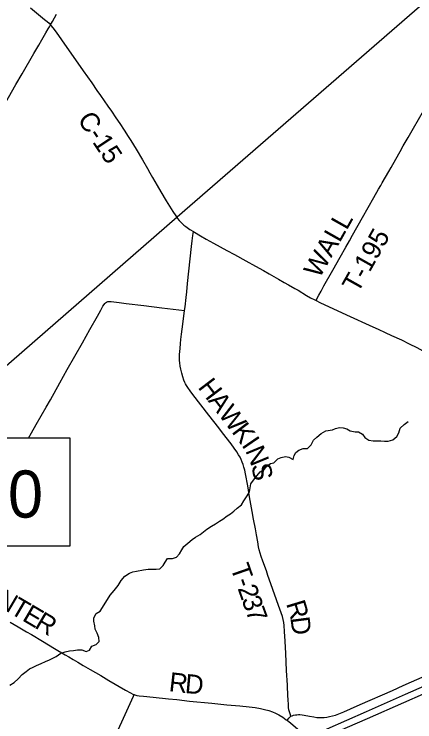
# Model space of a CAD drawing. Extents: x -1.4 to 35.4, y 0 to 22.
# Drawn here: x 6.307 to 7.497, y 14.844 to 16.946 of the extents above; entities that cross this region are included whole.
import ezdxf

# ---------------------------------------------------------------- set-up
doc = ezdxf.new("R2010")
doc.units = 0
for name, color, linetype in [('GM_X_County_Road', 7, 'Continuous'), ('GM_X_County_Road_Text', 7, 'Continuous'), ('GM_X_Interstate_Route', 7, 'Continuous'), ('GM_X_Minor_River', 7, 'Continuous'), ('GM_X_Rail_Line', 7, 'Continuous'), ('GM_X_Township_Road', 7, 'Continuous'), ('GM_X_Township_Road_Text', 7, 'Continuous'), ('SH_Data', 7, 'Continuous')]:
    doc.layers.add(name, color=color, linetype=linetype)

msp = doc.modelspace()

# ---------------------------------------------------------------- linework, layer by layer
at = {"layer": 'GM_X_County_Road'}
for points in [[(6.3553, 16.9645), (6.3974, 16.9305), (6.4045, 16.9244), (6.4103, 16.9187), (6.4148, 16.9138)], [(6.4148, 16.9138), (6.4202, 16.9236), (6.433, 16.9463)], [(6.1314, 16.4238), (6.133, 16.4266), (6.1492, 16.4545), (6.165, 16.482), (6.1706, 16.4916), (6.1833, 16.5137), (6.2038, 16.5492), (6.2225, 16.5822), (6.2338, 16.6015), (6.2506, 16.6305), (6.2598, 16.646), (6.2902, 16.6988), (6.3117, 16.7366), (6.3302, 16.7682), (6.3655, 16.8289), (6.3798, 16.8537), (6.389, 16.8699), (6.4011, 16.8909), (6.4076, 16.9022), (6.4116, 16.9085), (6.4139, 16.9122), (6.4148, 16.9138)], [(6.4148, 16.9138), (6.4162, 16.9123), (6.4221, 16.905), (6.4319, 16.8921), (6.4479, 16.87), (6.5119, 16.7775), (6.5371, 16.742), (6.5528, 16.7196), (6.5637, 16.7038), (6.5854, 16.6727), (6.5955, 16.6578), (6.609, 16.6376), (6.6205, 16.6206), (6.6332, 16.6015), (6.6456, 16.5828), (6.6535, 16.5702), (6.6688, 16.5453), (6.6881, 16.5127), (6.7027, 16.4874), (6.7098, 16.475), (6.7181, 16.4604), (6.7315, 16.4366), (6.7424, 16.4178), (6.7585, 16.3912), (6.7783, 16.3597), (6.7869, 16.3468), (6.7923, 16.3392), (6.7972, 16.3329), (6.8013, 16.3283), (6.8057, 16.3239), (6.8107, 16.3195), (6.8166, 16.315), (6.8289, 16.3066), (6.8392, 16.3)], [(6.8392, 16.3), (6.842, 16.2982), (6.8601, 16.2873), (6.8773, 16.2775), (6.8985, 16.2657), (6.9384, 16.2442), (6.9608, 16.232), (6.9951, 16.2132), (7.0234, 16.1976), (7.0468, 16.1847), (7.0645, 16.1744), (7.0915, 16.159), (7.1087, 16.149), (7.1211, 16.1419), (7.1401, 16.1313), (7.1498, 16.1257), (7.1754, 16.1104), (7.1872, 16.1035), (7.1998, 16.0969), (7.2033, 16.0951)], [(7.2033, 16.0951), (7.2148, 16.0895), (7.2939, 16.0532), (7.3717, 16.0173), (7.3881, 16.0097), (7.4089, 15.9999), (7.4275, 15.9915), (7.457, 15.9781), (7.4799, 15.967), (7.5026, 15.9554), (7.5207, 15.9457), (7.5512, 15.929), (7.575, 15.9159)], [(6.295, 15.1394), (6.3186, 15.1256), (6.3434, 15.1114), (6.3579, 15.1031), (6.3914, 15.0829), (6.4267, 15.062), (6.4587, 15.0429), (6.4694, 15.0367), (6.4817, 15.0294), (6.4956, 15.0212), (6.5122, 15.0114), (6.5326, 14.9994), (6.5642, 14.9809), (6.5877, 14.967), (6.637, 14.9381), (6.6523, 14.9297), (6.6597, 14.9262), (6.6631, 14.9248)], [(7.1288, 14.8603), (7.1323, 14.8618), (7.1365, 14.8631), (7.1421, 14.8643), (7.1464, 14.8649), (7.1509, 14.8652), (7.1553, 14.8652), (7.1621, 14.8646), (7.1683, 14.8638), (7.1836, 14.8608), (7.197, 14.8583), (7.2056, 14.857), (7.2117, 14.8565), (7.2197, 14.8564), (7.2277, 14.8568), (7.2357, 14.8576), (7.2436, 14.8591), (7.2526, 14.8613), (7.2614, 14.864), (7.2707, 14.8674), (7.2856, 14.8737), (7.3061, 14.8827), (7.3345, 14.8952), (7.43, 14.9372), (7.4623, 14.9518), (7.5277, 14.9806)], [(6.6073, 14.8032), (6.6262, 14.8438), (6.6608, 14.9198), (6.6631, 14.9248)], [(6.6631, 14.9248), (6.6649, 14.9241), (6.671, 14.9224), (6.6784, 14.921), (6.6908, 14.9196), (6.7192, 14.917), (6.765, 14.9123), (6.7897, 14.9098), (6.8274, 14.9056), (6.8941, 14.899), (6.9387, 14.8945), (6.9771, 14.8912), (7.0049, 14.8885), (7.0228, 14.8862), (7.038, 14.8835), (7.0507, 14.8807), (7.0632, 14.8771), (7.0737, 14.8735), (7.0828, 14.8697), (7.0932, 14.8642), (7.1042, 14.8574), (7.1149, 14.85), (7.1172, 14.8483)], [(7.1172, 14.8483), (7.1196, 14.8511), (7.1229, 14.8551), (7.1245, 14.8571), (7.1263, 14.8588), (7.1288, 14.8603)], [(7.1172, 14.8483), (7.1288, 14.8395), (7.1412, 14.8293), (7.1654, 14.8079), (7.1775, 14.7974), (7.187, 14.7892), (7.1941, 14.7829), (7.2107, 14.7682), (7.2318, 14.7498), (7.2401, 14.7424), (7.2517, 14.7312), (7.2634, 14.7192), (7.2728, 14.7086), (7.2869, 14.6913), (7.2992, 14.6749), (7.3325, 14.6315), (7.3479, 14.612), (7.367, 14.5874), (7.404, 14.5399), (7.4146, 14.5268), (7.4218, 14.5191), (7.4291, 14.5122), (7.4412, 14.5024), (7.4838, 14.4696)]]:
    msp.add_lwpolyline(points, dxfattribs=at)
at = {"layer": 'GM_X_Interstate_Route'}
for points in [[(7.1775, 14.7974), (7.3529, 14.8749), (7.4687, 14.9264), (7.525, 14.9511), (7.5615, 14.967), (7.6523, 15.0074), (7.7172, 15.0359), (7.815, 15.0791), (7.9138, 15.1229), (7.99, 15.1564), (8.0805, 15.1961), (8.1709, 15.2359), (8.259, 15.2748), (8.4153, 15.3438), (8.5061, 15.3843), (8.6167, 15.4332), (8.6294, 15.4388), (8.6972, 15.4682), (8.7732, 15.5025), (8.8738, 15.5467), (8.9586, 15.584), (8.9661, 15.5874), (9, 15.6025)], [(5.8055, 14.2012), (5.9449, 14.2585), (6.0761, 14.3136), (6.1865, 14.3589), (6.4314, 14.461), (6.5077, 14.4927), (6.5331, 14.5032), (6.5439, 14.5076), (6.63, 14.5433), (6.7276, 14.5836), (7.0293, 14.7094), (7.1941, 14.7829), (7.2443, 14.8054), (7.356, 14.8539), (7.4642, 14.9013), (7.5228, 14.9272), (7.5403, 14.935), (7.7166, 15.0125), (7.795, 15.0474), (7.9308, 15.1073), (7.9405, 15.1115)]]:
    msp.add_lwpolyline(points, dxfattribs=at)
at = {"layer": 'GM_X_Minor_River'}
for points in [[(6.9987, 15.515), (7.0058, 15.527), (7.0075, 15.5387), (7.0096, 15.5508), (7.0175, 15.5621), (7.0287, 15.5755), (7.0377, 15.5867), (7.0488, 15.593), (7.0574, 15.6034), (7.0682, 15.6112), (7.0781, 15.6129), (7.0897, 15.6248), (7.0997, 15.6292), (7.1126, 15.6323), (7.1228, 15.6298), (7.1356, 15.6235), (7.1381, 15.6345), (7.1429, 15.6442), (7.1525, 15.6505), (7.1647, 15.6556), (7.178, 15.6561), (7.1889, 15.6669), (7.196, 15.68), (7.2057, 15.6897), (7.2188, 15.7004), (7.2326, 15.7081), (7.2517, 15.7116), (7.2612, 15.7148), (7.2734, 15.7176), (7.284, 15.7174), (7.2946, 15.7141), (7.3047, 15.7082), (7.3195, 15.7053), (7.3294, 15.7055), (7.341, 15.6984), (7.3484, 15.688), (7.36, 15.6802), (7.3725, 15.6788), (7.3827, 15.6786), (7.3957, 15.6787), (7.4066, 15.6777), (7.4173, 15.6779), (7.431, 15.681), (7.4434, 15.691), (7.4489, 15.7019), (7.4534, 15.7163), (7.465, 15.7271), (7.4773, 15.7363)], [(6.2942, 14.953), (6.3073, 14.9603), (6.3189, 14.9714), (6.3305, 14.9841), (6.3425, 14.993), (6.3525, 15.0008), (6.3628, 15.0059), (6.3728, 15.011), (6.3874, 15.0172), (6.4004, 15.0234), (6.4115, 15.0281), (6.4219, 15.0332), (6.4318, 15.0379), (6.4453, 15.0475), (6.4579, 15.0515), (6.4716, 15.0546), (6.4831, 15.0559), (6.4945, 15.0572), (6.5078, 15.0573), (6.5202, 15.0525), (6.5305, 15.0565), (6.5376, 15.0685), (6.5499, 15.0739), (6.5595, 15.0821), (6.5579, 15.0947), (6.5536, 15.1069), (6.5477, 15.1195), (6.546, 15.1291), (6.5436, 15.1428), (6.5438, 15.153), (6.5502, 15.1658), (6.5625, 15.1724), (6.5695, 15.1837), (6.577, 15.1964), (6.5836, 15.2069), (6.5919, 15.2197), (6.6039, 15.2339), (6.6152, 15.2484), (6.625, 15.2638), (6.6359, 15.2765), (6.6494, 15.2854), (6.6593, 15.2897), (6.6704, 15.2914), (6.6913, 15.2952), (6.705, 15.2975), (6.7187, 15.2976), (6.7282, 15.2975), (6.7392, 15.2984), (6.7497, 15.308), (6.7552, 15.3178), (6.7626, 15.3294), (6.777, 15.3291), (6.7889, 15.3327), (6.7978, 15.3424), (6.8049, 15.3548), (6.8108, 15.3649), (6.8224, 15.3742), (6.8359, 15.3857), (6.8455, 15.3923), (6.8593, 15.4004), (6.8694, 15.4082), (6.879, 15.4163), (6.8932, 15.4252), (6.9052, 15.4322), (6.9167, 15.4395), (6.9263, 15.4462), (6.9398, 15.4554), (6.9494, 15.4616), (6.9591, 15.4698), (6.9695, 15.478), (6.9822, 15.4887), (6.9893, 15.5007), (6.9987, 15.515)]]:
    msp.add_lwpolyline(points, dxfattribs=at)
at = {"layer": 'GM_X_Rail_Line'}
msp.add_lwpolyline([(9, 17.2368), (8.179, 17.3686), (8.1053, 17.377), (7.9738, 17.3461), (7.5333, 16.988), (6.7907, 16.343), (6.0366, 15.6863)], dxfattribs=at)
at = {"layer": 'GM_X_Township_Road'}
for points in [[(7.2033, 16.0951), (7.2048, 16.098), (7.2117, 16.111), (7.2181, 16.1231), (7.2268, 16.1389), (7.2535, 16.1859), (7.2753, 16.2243), (7.292, 16.2534), (7.3029, 16.2729), (7.312, 16.2892), (7.3408, 16.3414), (7.3751, 16.4012), (7.3892, 16.4261), (7.3954, 16.4368), (7.4001, 16.4448), (7.4098, 16.4615), (7.4196, 16.4788), (7.4261, 16.4901), (7.4398, 16.5152), (7.4528, 16.5376), (7.4625, 16.5545), (7.4766, 16.5793), (7.4926, 16.6073), (7.5371, 16.6843)], [(6.8129, 16.0656), (6.8143, 16.0763), (6.8176, 16.1047), (6.8192, 16.1208), (6.8219, 16.1461), (6.8336, 16.2555), (6.8356, 16.2721), (6.8378, 16.2888), (6.8392, 16.3)], [(6.3492, 15.6863), (6.358, 15.7019), (6.3722, 15.7267), (6.4017, 15.7786), (6.4144, 15.8006), (6.4425, 15.8504), (6.4647, 15.8899), (6.51, 15.9692), (6.532, 16.0094), (6.554, 16.0483), (6.5639, 16.0662), (6.5706, 16.0782), (6.5739, 16.0831), (6.5763, 16.0862), (6.5784, 16.0883), (6.5808, 16.0902), (6.5835, 16.0915), (6.5851, 16.0921), (6.5881, 16.0926), (6.5911, 16.0928), (6.5954, 16.0926), (6.6188, 16.0895), (6.6398, 16.0866), (6.6916, 16.0803), (6.7452, 16.0737), (6.8129, 16.0656)], [(7.1288, 14.8603), (7.1264, 14.8674), (7.1245, 14.8733), (7.1229, 14.8798), (7.1218, 14.8859), (7.1211, 14.8932), (7.1203, 14.9106), (7.1198, 14.9199), (7.1183, 14.9522), (7.116, 14.9962), (7.1137, 15.0471), (7.1117, 15.0831), (7.1097, 15.1123), (7.1083, 15.1303), (7.1072, 15.139), (7.1056, 15.1476), (7.1032, 15.1566), (7.0999, 15.1674), (7.0919, 15.1896), (7.0689, 15.254), (7.0603, 15.2786), (7.0557, 15.2922), (7.0455, 15.3209), (7.0406, 15.3349), (7.0374, 15.3449), (7.0348, 15.3545), (7.0328, 15.3636), (7.03, 15.3782), (7.0265, 15.399), (7.0233, 15.4174), (7.0179, 15.4461), (7.014, 15.4681), (7.0061, 15.5122), (7.0003, 15.5452), (6.994, 15.5807), (6.9916, 15.5917), (6.9893, 15.6007), (6.987, 15.6079), (6.9842, 15.6155), (6.981, 15.623), (6.9777, 15.6297), (6.9734, 15.6373), (6.968, 15.6458), (6.9602, 15.657), (6.9509, 15.6695), (6.9256, 15.7026), (6.9145, 15.7168), (6.8853, 15.7547), (6.8377, 15.8161), (6.8291, 15.8274), (6.8226, 15.8365), (6.8186, 15.8427), (6.816, 15.8476), (6.8139, 15.852), (6.8111, 15.8589), (6.808, 15.8683), (6.8048, 15.8796), (6.8019, 15.891), (6.8002, 15.9001), (6.7987, 15.9106), (6.7981, 15.9173), (6.7978, 15.9266), (6.7979, 15.9305), (6.7981, 15.9346), (6.7996, 15.9525), (6.8009, 15.9673), (6.8021, 15.979), (6.8039, 15.9956), (6.8074, 16.0252), (6.8129, 16.0656)]]:
    msp.add_lwpolyline(points, dxfattribs=at)
at = {"layer": 'SH_Data'}
msp.add_lwpolyline([(6.4729, 15.6863), (5.2029, 15.6863), (5.2029, 15.5687), (4.8097, 14.8479), (5.2029, 15.4463), (5.2029, 15.3663), (6.4729, 15.3663)], close=True, dxfattribs=at)

# ---------------------------------------------------------------- texts
at = {"layer": 'GM_X_County_Road_Text'}
for s, height, rotation, p in [('C-15', 0.05682, 303.6894, (6.4932, 16.633)), ('N', 0.0568, 329.5236, (6.2482, 15.1932)), ('T', 0.0568, 329.5437, (6.2913, 15.1678)), ('E', 0.0568, 329.5386, (6.3279, 15.1463)), ('R', 0.0568, 329.5469, (6.3646, 15.1248)), ('R', 0.0568, 353.523, (6.7646, 14.935)), ('D', 0.0568, 354.8882, (6.8124, 14.9296))]:
    msp.add_text(s, height=height, rotation=rotation, dxfattribs=at).set_placement(p)
at = {"layer": 'GM_X_Township_Road_Text'}
for s, height, rotation, p in [('WALL', 0.05682, 60.5762, (7.2133, 16.1586)), ('T-195', 0.05682, 60.6738, (7.3273, 16.1146)), ('H', 0.0568, 307.2371, (6.8506, 15.8373)), ('A', 0.0568, 307.2357, (6.8809, 15.7974)), ('W', 0.0568, 307.2329, (6.9111, 15.7576)), ('K', 0.0568, 307.1264, (6.9509, 15.7053)), ('I', 0.0568, 304.4338, (6.9807, 15.666)), ('N', 0.0568, 292.4562, (6.9924, 15.6495)), ('S', 0.0568, 281.5601, (7.0107, 15.606)), ('T', 0.0568, 289.2197, (6.9481, 15.3028)), ('-', 0.0568, 289.2268, (6.9621, 15.2627)), ('2', 0.0568, 289.2641, (6.9698, 15.2406)), ('3', 0.0568, 289.4272, (6.9814, 15.2074)), ('R', 0.0568, 286.8772, (7.1139, 15.1952)), ('7', 0.0568, 290.0743, (6.9933, 15.1737)), ('D', 0.0568, 277.2543, (7.127, 15.153))]:
    msp.add_text(s, height=height, rotation=rotation, dxfattribs=at).set_placement(p)
at = {"layer": 'SH_Data'}
msp.add_text('CLI-380-0500', height=0.14, dxfattribs=at).set_placement((5.2477, 15.4504))

doc.saveas('drawing.dxf')
